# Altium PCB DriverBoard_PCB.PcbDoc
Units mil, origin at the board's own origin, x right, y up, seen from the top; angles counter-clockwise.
Board outline 2560 x 1120 mil, 4 copper layers (Top Layer, GND, PWR, Bottom Layer), stack 62.449 mil thick; 35 components, 27 nets, 120 pads, 83 vias.
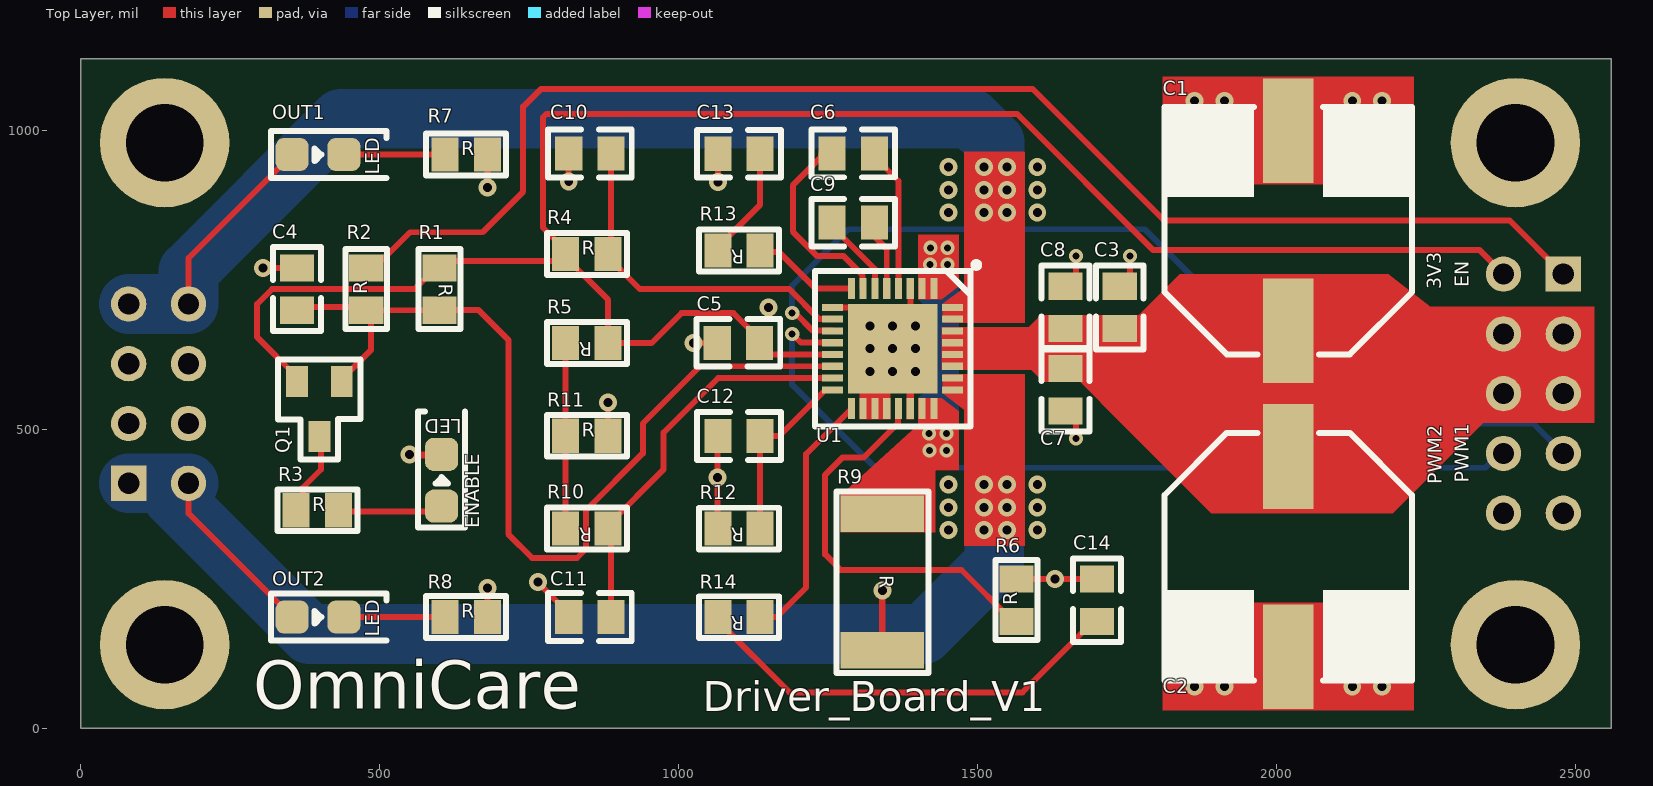
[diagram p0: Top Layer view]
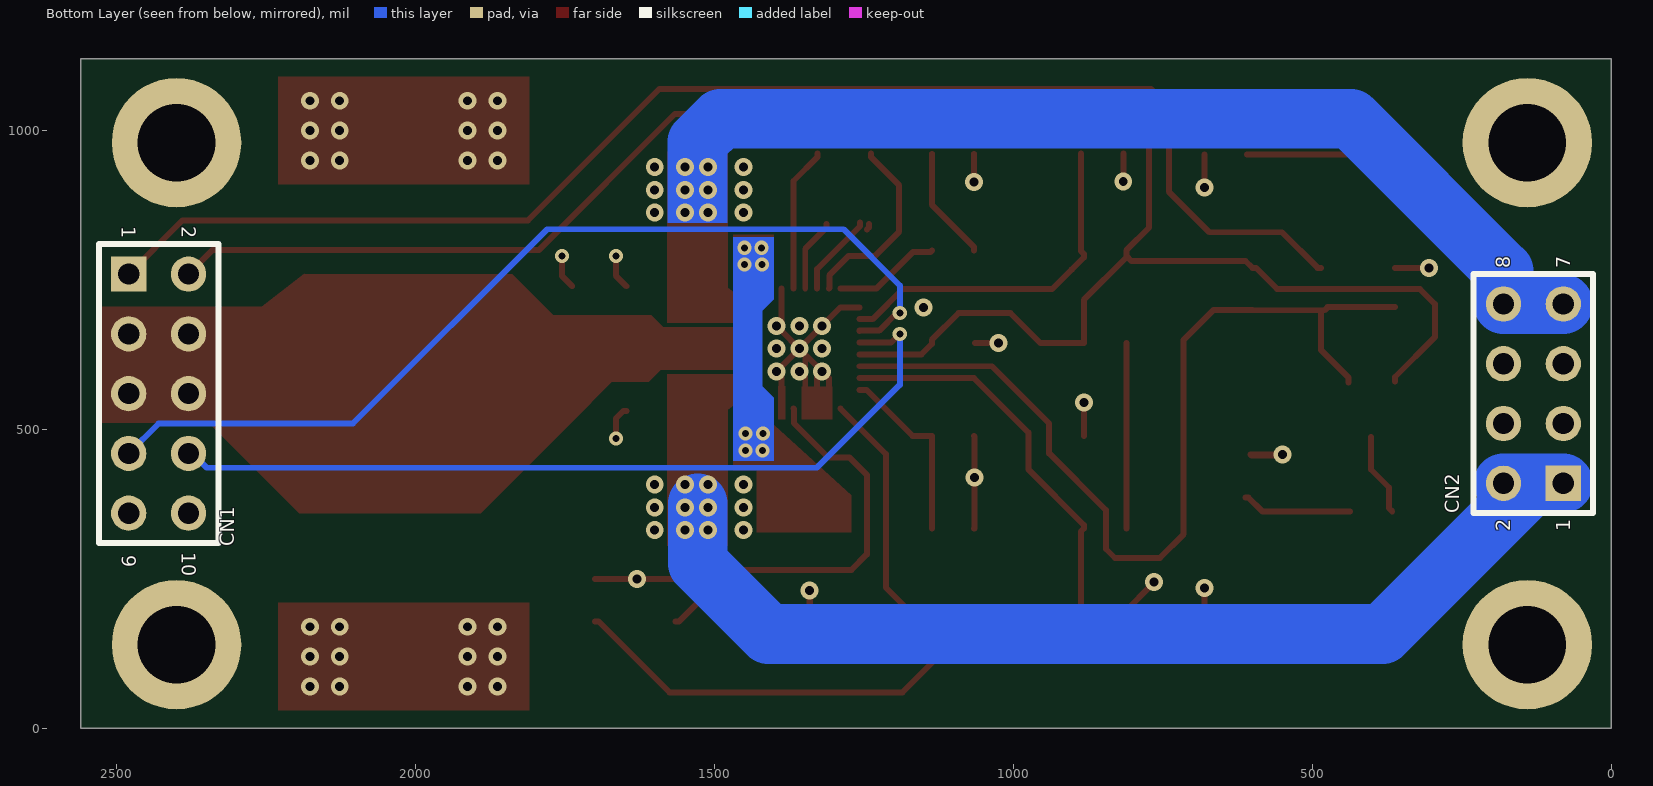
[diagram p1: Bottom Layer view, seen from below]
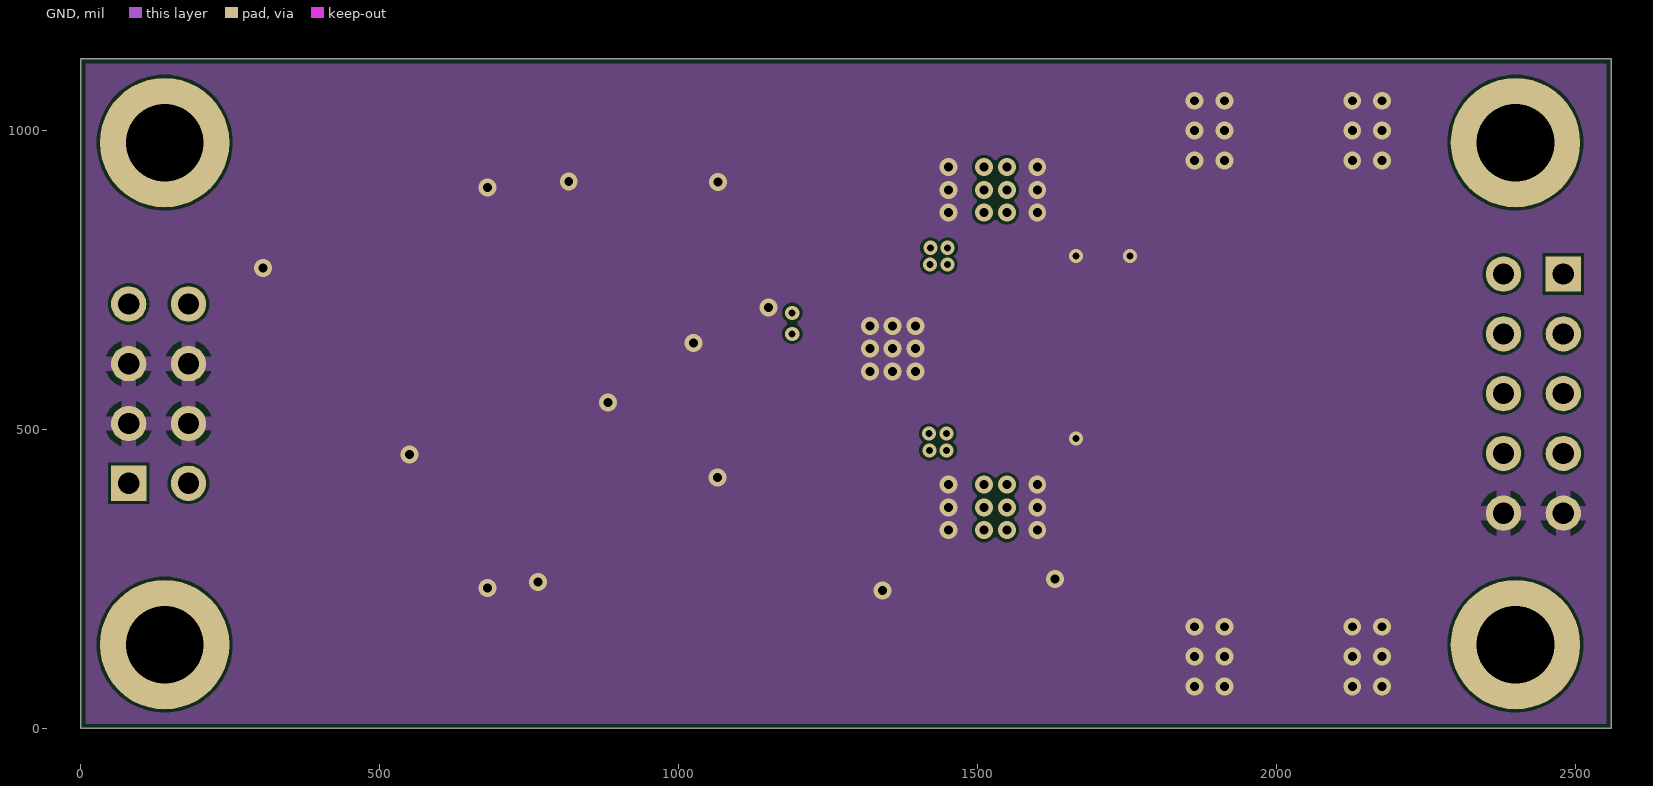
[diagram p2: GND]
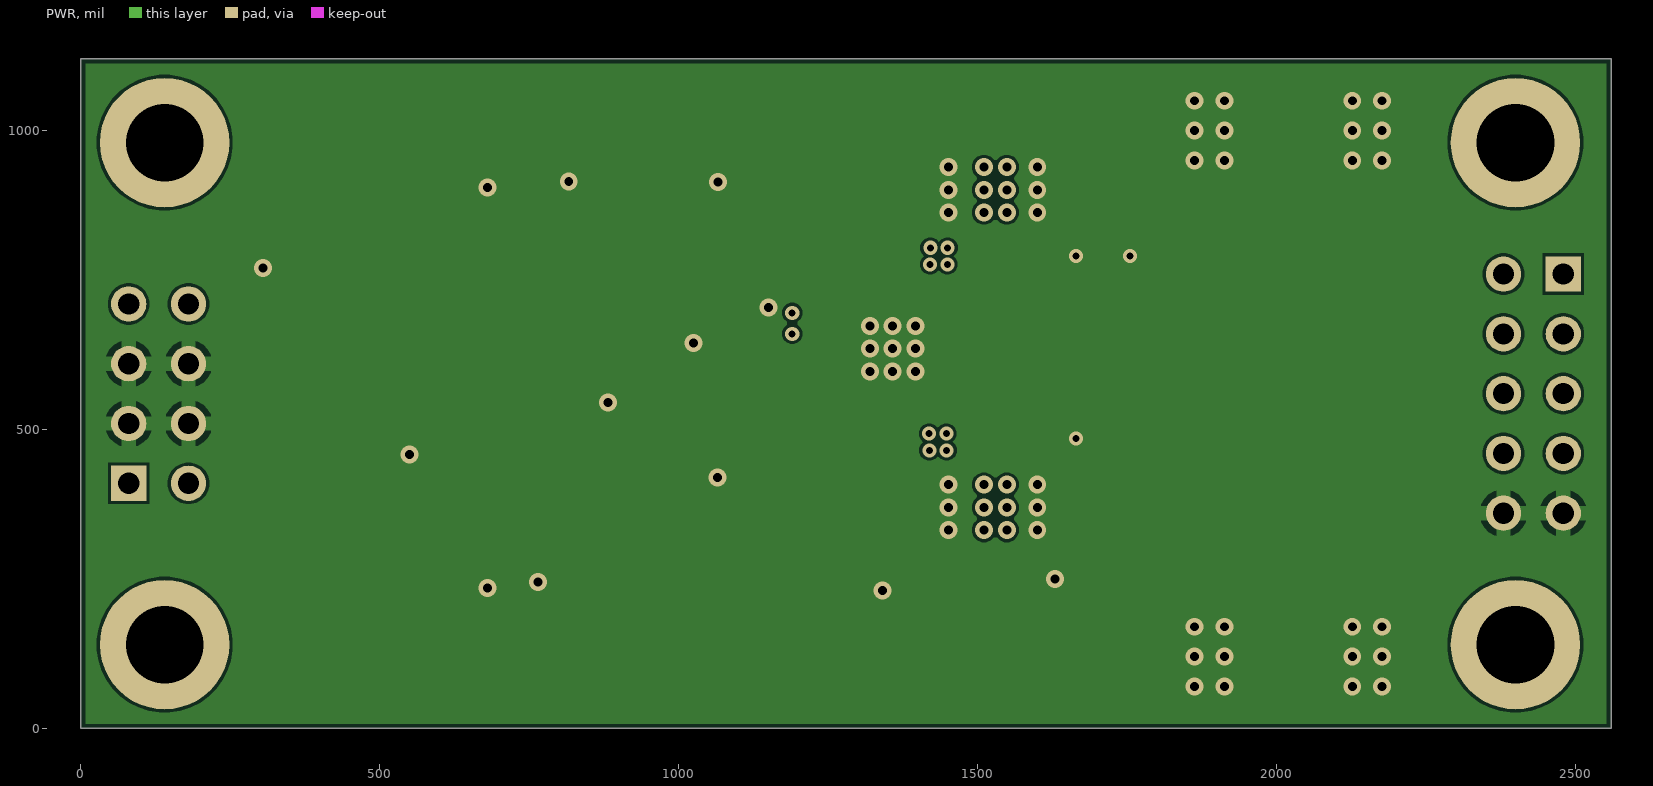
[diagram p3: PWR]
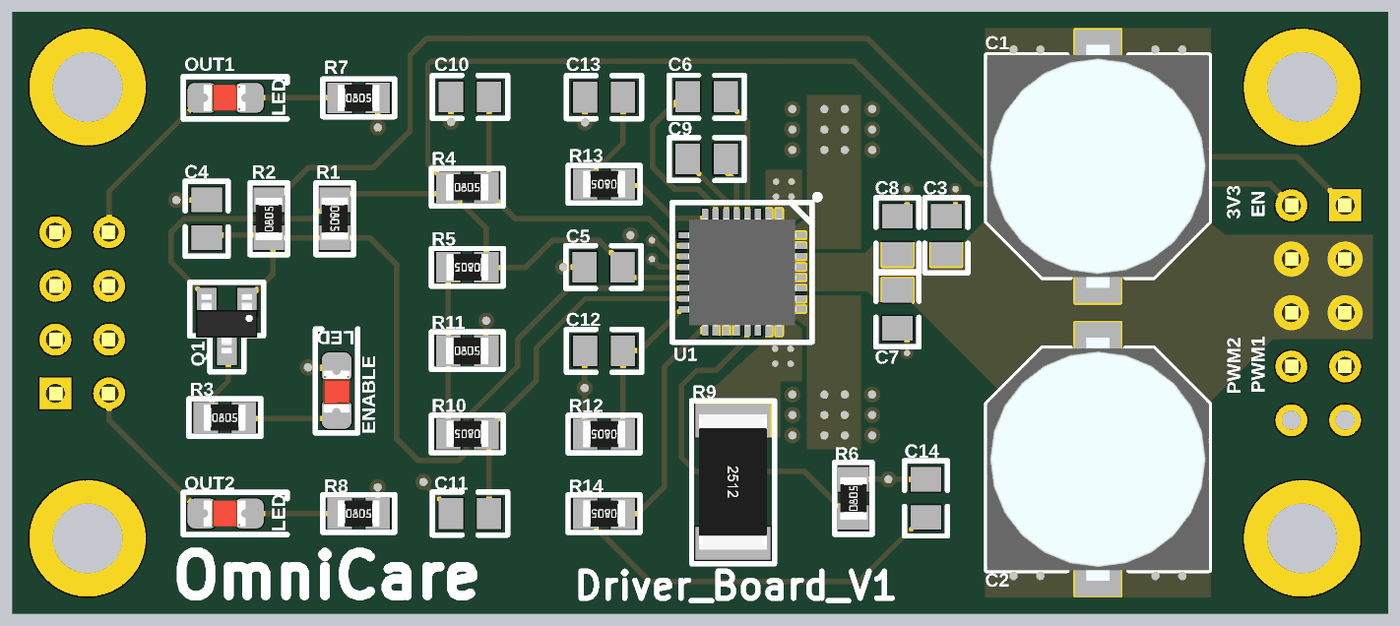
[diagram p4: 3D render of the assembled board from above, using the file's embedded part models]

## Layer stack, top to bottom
Top Solder: solder mask 0.5, Solder Resist, Dk 3.8
Top Layer: signal copper 1.378
Dielectric 1: prepreg 8.2835, 7628, Dk 4.6
GND: signal copper 0.5984
Core: core 41.9291, FR-4, Dk 4.5
PWR: signal copper 0.5984
Dielectric 2: prepreg 8.2835, 7628, Dk 4.6
Bottom Layer: signal copper 1.378
Bottom Solder: solder mask 0.5, Solder Resist, Dk 3.8

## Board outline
0,0 0,1120 2560,1120 2560,0

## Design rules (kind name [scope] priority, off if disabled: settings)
BoardOutlineClearance [All] p1: gap=7.87 ignorepadtopadclearanceinfootprint=FALSE
Clearance [All] p1: gap=5 ignorepadtopadclearanceinfootprint=FALSE except(9.84: Arc-Hole Track-Hole SMDPad-Hole THPad-Hole Via-Hole Fill-Hole Poly-Hole Region-Hole Text-Hole)
ComponentClearance [All] p1: gap=5 collisioncheckmode=3 verticalgap=5 showdistances=TRUE
DiffPairsRouting [All] p1: maxlimit=10 minlimit=5 mostfreqgap=10 toplayer_prefgap=5 toplayer_minwidth=5 toplayer_maxwidth=1000 toplayer_prefwidth=5 midlayer1_mingap=10 midlayer1_minwidth=15 midlayer1_maxwidth=15 midlayer1_prefwidth=15 midlayer2_mingap=10 midlayer2_minwidth=15 midlayer2_maxwidth=15 midlayer2_prefwidth=15 bottomlayer_prefgap=5 bottomlayer_minwidth=5 bottomlayer_maxwidth=1000 bottomlayer_prefwidth=5 maxuncoupledlength=500
Height [All] p1: minheight=0 maxheight=71497.94 prefheight=500
HoleSize [All] p1: absolutevalues=TRUE maxlimit=248.03 minlimit=11.81 maxpercent=80.000 minpercent=20.000
HoleToHoleClearance [All] p1: gap=9.84 allowstackedmicrovias=FALSE
MinimumAnnularRing [All] p1: minimumring=3
MinimumSolderMaskSliver [All] p1: minsoldermaskwidth=0
PlaneClearance [All] p1: clearance=5
PlaneConnect PlaneConnectPowerPads [InPadClass('PowerPads')] p1: planeconnectstyle=Direct reliefexpansion=20 reliefentries=4 reliefconductorwidth=10 reliefairgap=10
PlaneConnect [All] p2: planeconnectstyle=Relief reliefexpansion=11.81 reliefentries=4 reliefconductorwidth=25 reliefairgap=5
PolygonConnect PolygonConnectPowerPads [All vs (InPadClass('PowerPads'))] p1: connectstyle=Direct reliefconductorwidth=10 reliefentries=4 polygonreliefangle="90 Angle" airgapwidth=10
PolygonConnect [All] p2: thpad.connectstyle=Relief thpad.reliefconductorwidth=25 thpad.reliefentries=4 thpad.polygonreliefangle="90 Angle" thpad.airgapwidth=10 smdpad.connectstyle=Relief smdpad.reliefconductorwidth=5 smdpad.reliefentries=4 smdpad.polygonreliefangle="90 Angle" smdpad.airgapwidth=5 via.connectstyle=Direct via.reliefconductorwidth=5 via.reliefentries=4 via.polygonreliefangle="90 Angle" via.airgapwidth=5
RoutingVias [All] p1: holewidth=11.81 width=23.62 viastyle="Through Hole" minholewidth=11.81 minwidth=23.62 maxholewidth=23.62 maxwidth=259.84
SilkToSilkClearance [All] p1: silktosilkclearance=0
SilkToSolderMaskClearance [IsPad] p1: minsilkscreentomaskgap=5 clearancetoexposedcopper=TRUE
SolderMaskExpansion [All] p1: expansion=2.95 istentingtop=FALSE
SupplyNets "Schematic Supply Nets_3" [InNet('GND')] p1: voltage=0.000
SupplyNets "Schematic Supply Nets_2" [InNet('VIN_MOTORS')] p2: voltage=0.000
SupplyNets "Schematic Supply Nets_1" [InNet('+3V3_MCU')] p3: voltage=0.000
Width [All] p1: maxlimit=1000 minlimit=5 preferedwidth=5 midlayer1_maxwidth=10 midlayer2_maxwidth=10 minimp=50.000000 maximp=50.000000 favimp=50.000000
20 further rules are at their usual default settings.

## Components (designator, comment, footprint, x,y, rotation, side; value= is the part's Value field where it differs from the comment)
C1 "220u" "CAP SMD ELE 10x10.2mm" 2018,832.68 r270 top
C2 "220u" "CAP SMD ELE 10x10.2mm" 2022,287.32 r90 top
C3 "100n" "CAP SMD CER 0805" 1738,704.24 r90 top
C4 "10n" "CAP SMD CER 0805" 361.57,734.94 r90 top
C5 "220n" "CAP SMD CER 0805" 1100,645 r180 top
C6 "1u" "CAP SMD CER 0805" 1292,962 r180 top
C7 "470n" "CAP SMD CER 0805" 1647,566.44 r270 top
C8 "470n" "CAP SMD CER 0805" 1647,704.24 r90 top
C9 "100n" "CAP SMD CER 0805" 1292,846 r180 top
C10 "1n" "CAP SMD CER 0805" 851.57,961.65 r180 top
C11 "100n" "CAP SMD CER 0805" 851.57,186.34 r180 top
C12 "1n" "CAP SMD CER 0805" 1101,489.16 r180 top
C13 "100p" "CAP SMD CER 0805" 1101,961.34 r180 top
C14 "100p" "CAP SMD CER 0805" 1700,214.57 r90 top
CN1 "CON HEADER 2.54mm 2x5" "CON HEADER 2.54mm 2x5" 2480,760 r270 bottom
CN2 "Header 2x4 Male" "Header 2x4 Male-Footprint-1" 80,410 r90 bottom
ENABLE "RED" "LED SMD 0805" 603.39,413.39 r90 top
OUT1 "RED" "LED SMD 0805" 395,960 r0 top
OUT2 "RED" "LED SMD 0805" 395,186.34 r0 top
Q1 "BSS84" SOT23 398.97,534.1 r0 top
R1 "39K" "RES SMD 0805" 600,734.94 r270 top
R2 "1K" "RES SMD 0805" 477.29,734.94 r90 top
R3 "330R" "RES SMD 0805" 395.43,365 r0 top
R4 "22K" "RES SMD 0805" 846.5,793.69 r0 top
R5 "330R" "RES SMD 0805" 846.5,644.53 r180 top
R6 "5K" "RES SMD 0805" 1565,214.57 r90 top
R7 "10K" "RES SMD 0805" 644.57,960 r0 top
R8 "10K" "RES SMD 0805" 644.57,186.34 r0 top
R9 "0R05" "RES SMD 2512" 1341,245 r270 top
R10 "13K" "RES SMD 0805" 846.5,334.41 r180 top
R11 "220R" "RES SMD 0805" 846.5,489.47 r0 top
R12 "22K" "RES SMD 0805" 1101,334.09 r180 top
R13 "4K7" "RES SMD 0805" 1101,799.28 r180 top
R14 "4K7" "RES SMD 0805" 1101,186.02 r180 top
U1 "STSPIN958" "NBG32 (VFQFPN 32)" 1358,635.34 r270 top

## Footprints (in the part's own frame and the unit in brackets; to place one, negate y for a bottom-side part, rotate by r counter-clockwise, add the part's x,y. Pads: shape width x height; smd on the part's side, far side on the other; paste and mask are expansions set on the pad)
"CAP SMD CER 0805" [mm] "Ceramicic SMD Capacitor"
  rect 1.15x1.45 smd: 1(-0.9,0) 2(0.9,0)
  silkscreen extent -1.78,-1.02 1.78,1.02, body extent -1,-0.63 1,0.63
"CAP SMD ELE 10x10.2mm" [mm]
  rect 4.45x2.15 smd: 1(4.25,0.051) 2(-4.25,0.051)
  silkscreen extent -5.26,-5.21 5.26,5.31, body extent -5.75,-5.2 5.75,5.3, height 11
"CON HEADER 2.54mm 2x5" [mm]
  rect 1.5x1.5 hole 0.9: 1(0,0)
  round 1.5 hole 0.9: 2(0,2.54) 3(2.54,0) 4(2.54,2.54) 5(5.08,0) 6(5.08,2.54) 7(7.62,0) 8(7.62,2.54) 9(10.16,0) 10(10.16,2.54)
  silkscreen extent -1.27,-1.27 11.43,3.81, body extent -1.27,-1.22 8.89,3.76, height 8.6
"Header 2x4 Male-Footprint-1" [mm]
  rect 1.5x1.5 hole 0.9: 1(0,0)
  round 1.5 hole 0.9: 2(0,2.54) 3(2.54,0) 4(2.54,2.54) 5(5.08,0) 6(5.08,2.54) 7(7.62,0) 8(7.62,2.54)
  silkscreen extent -1.27,-1.27 8.89,3.81, body extent -1.27,-1.22 8.89,3.76, height 8.6
"LED SMD 0805" [mm]
  rrect50% 1.4x1.4 smd: 1(-1.057,0) 2(1.143,0)
  silkscreen extent -1.96,-1 2.96,1, body extent -1,-0.63 1,0.63, height 0.8
"NBG32 (VFQFPN 32)" [mm]
  rect 0.9x0.3 smd: 1(-2.55,1.75) 2(-2.55,1.25) 3(-2.55,0.75) 4(-2.55,0.25) 5(-2.55,-0.25) 6(-2.55,-0.75) 7(-2.55,-1.25) 8(-2.55,-1.75) 17(2.55,-1.75) 18(2.55,-1.25) 19(2.55,-0.75) 20(2.55,-0.25) 21(2.55,0.25) 22(2.55,0.75) 23(2.55,1.25) 24(2.55,1.75)
  rect 0.3x0.9 smd: 9(-1.75,-2.55) 10(-1.25,-2.55) 11(-0.75,-2.55) 12(-0.25,-2.55) 13(0.25,-2.55) 14(0.75,-2.55) 15(1.25,-2.55) 16(1.75,-2.55) 25(1.75,2.55) 26(1.25,2.55) 27(0.75,2.55) 28(0.25,2.55) 29(-0.25,2.55) 30(-0.75,2.55) 31(-1.25,2.55) 32(-1.75,2.55)
  rect 3.8x3.8 smd: 33(0,0)
  silkscreen extent -3.68,-3.3 3.3,3.68, body extent -2.55,-2.55 2.55,2.55, height 1
"RES SMD 0805" [mm]
  rect 1.15x1.45 smd: 1(-0.9,0) 2(0.9,0)
  silkscreen extent -1.7,-0.89 1.7,0.89, body extent -1.01,-0.63 0.99,0.62, height 0.52
"RES SMD 2512" [mm]
  rect 1.55x3.55 smd: 1(-2.9,0) 2(2.9,0)
  silkscreen extent -3.84,-1.96 3.86,1.96, body extent -3.2,-1.6 3.2,1.6, height 0.3
SOT23 [mm]
  rect 0.92x1.32 smd: 1(0.95,1.166) 2(-0.95,1.166) 3(0.003,-1.166)
  silkscreen extent -1.75,-2.13 1.74,2.1, body extent -1.45,-1.27 1.45,1.53, height 1.3

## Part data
C1 C2: library part "CAP SMD - Gen. Electrolytic", "Generic electrolytic capacitors for general purpose."
C3 C4 C5 C6 C7 C8 C9 C10 C11 C12 C13 C14: library part "CAP SMD - Gen. Ceramic 0805", "Generic ceramic capacitor with package 0805 for general purpose."
CN2: library part CMP-00003-1, "Pin Header  2x4 Male 2.54mm"
ENABLE OUT1 OUT2: library part "LED SMD - Gen. 0805", "LED - SMD - 0805", Supplier Part Number 1=C84256
Q1: "TRANSISTOR - Mosfet  P Channel - 130 mA - 50VDS - 20VGS - SOT23"
R1 R2 R3 R4 R5 R6 R7 R8 R10 R11 R12 R13 R14: library part "RES SMD - Gen. 0805", "Generic resistor with package 0805 for general purpose"
R9: library part "RES SMD - Gen. 2512", "Generic resistor with package 2512 for general purpose"
U1: "ST Motor driver up to 58V"

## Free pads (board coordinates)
  round 216.53 hole 129.92: MECH(140,140) MECH(140,980) MECH(2400,140) MECH(2400,980)

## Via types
v1: diameter 30, hole 15, Top Layer to Bottom Layer, tented both sides, 70 vias
v2: diameter 23.62, hole 11.81, Top Layer to Bottom Layer, tented both sides, 13 vias

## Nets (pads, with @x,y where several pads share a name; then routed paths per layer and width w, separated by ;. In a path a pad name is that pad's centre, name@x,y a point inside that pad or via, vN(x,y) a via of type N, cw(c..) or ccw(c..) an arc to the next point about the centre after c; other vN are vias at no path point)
+3V3_MCU: C5.1 CN1.2 Q1.2 R1.1 R4.1 R5.1 U1.13 | length 3276.4
  Top Layer w10: Q1.2 361.57,587.87 295,654.44 295,710 320,735 558.72,735 594.09,770.37 R1.1 611.63,782 802.56,782 811.07,790.51 811.07,787.79 881.94,716.92 R5.1 954.53,644.53 1005,695 1091.56,695 1136.43,650.13 1136.43,643.13 1154.07,625.5 U1.13 ; R4.1 811.07,799.6 773,837.67 773,1022.14 778.86,1028 1566,1028 1794,800 2340,800 CN1.2
EN_MCU: CN1.1 R2.2 | length 2330.7
  Top Layer w10: R2.2@485,770.43 490.91,770.43 550.47,830 672,830 740,898 740,1040 770,1070 1592,1070 1812,850 2390,850 CN1.1
EN_nFAULT: C4.1 Q1.1 R1.2 R2.1 U1.14 | length 1600.2
  Top Layer w10: C4.1@361.57,704.57 474.09,704.57 479.16,699.5 R2.1@485,699.5 ; Q1.1@438.97,578.85 438.97,586.72 485,632.76 R2.1@485,699.5 ; U1.14 1035.81,605.81 940,510 940,460 845,365 845,300 830,285 755,285 715,325 715,650 665.43,699.57 600.06,699.57 R1.2 R2.1@485,699.5
GND: C1.2 C2.2 C3.2 C4.2 C5.2 C7.2 C8.2 C10.2 C11.2 C12.2 C13.2 C14.2 CN1.9 CN1.10 CN2.3 CN2.4 CN2.5 CN2.6 ENABLE.2 R6.2 R7.2 R8.2 R9.2 R11.2 R12.2 U1.3 U1.9 U1.18 U1.19 U1.20 U1.22 U1.33 | length 1817.1
  Top Layer w10: v1(305,770) 361.2,770 C4.2 ; v1(550,458.39) ENABLE.2 601.77,456.77 v1@559.25,456.77 ; R8.2 v1(680,235) ; v1@680,910 R7.2 ; v1(765,245) 765,243.38 816.13,192.24 C11.2 ; v1(816.13,915) C10.2 ; R11.2 v1@881.94,540 ; v1(1025,645) C5.2 ; R12.2 1065,334.66 1065,488.59 C12.2 ; v1(1065.57,914) C13.2 ; U1.9 1289.1,704.24 v1(1358,635.34) ; U1.18 1308.79,586.13 U1.33@1328.47,605.81 ; U1.19 U1.33@1328.47,605.81 ; v1@1340,223 1340,131.83 R9.2 v1(1341,231) v1@1341,223 ; U1.20 U1.33@1348.16,625.5 ; U1.22 1387.53,605.81 v1(1358,635.34) ; U1.3 1387.53,664.87 v1(1358,635.34) ; R6.2 C14.2 ; C7.2 1652.36,531.01 1665,518.37 v2(1665,485) ; C8.2 1647.36,739.67 1665,757.31 v2(1665,790) ; C3.2 1755,756.67 v2(1755,790) ; U1.33@1328.47,605.81 U1.33@1348.16,625.5 ; U1.33@1348.16,625.5 v1(1358,635.34)
  other v1: 1863,70 1913,70 2127,70 2177,70 1863,120 1913,120 2127,120 2177,120 1863,170 1913,170 2127,170 2177,170 1630,250 1451.5,331.68 1600,331.68 1451.5,369.68 1600,369.68 1451.5,407.68 1600,407.68 1065,420 881.94,545 1320,597.34 1358,597.34 1396,597.34 1320,635.34 1396,635.34 1320,673.34 1358,673.34 1396,673.34 1150,704.24 1451.5,863 1600,863 1451.5,901 1600,901 680,905 1451.5,939 1600,939 1863,950 1913,950 2127,950 2177,950 1863,1000 1913,1000 2127,1000 2177,1000 1863,1050 1913,1050 2127,1050 2177,1050
NetC6_1: C6.1 U1.4 | length 243
  Top Layer w10: C6.1 1327.43,956.09 1367.84,915.69 U1.4
NetC6_2: C6.2 U1.7 | length 320.5
  Top Layer w10: C6.2@1238.57,962 1238.57,956.09 1191,908.53 1191,831 1232,790 1276,790 1307.98,758.02 1307.98,736.54 U1.7
NetC9_1: C9.1 U1.5 | length 123.1
  Top Layer w10: C9.1@1312.43,844 1312.43,838.09 1348.16,802.37 U1.5
NetC9_2: C9.2 U1.6 | length 151.2
  Top Layer w10: C9.2@1241.57,844 1241.57,838.09 C9.2@1245.11,834.55 ; C9.2 1256.57,840.09 1328.13,768.53 1328.47,768.53 U1.6
NetC10_1: C10.1 R4.2 U1.10 | length 594.4
  Top Layer w10: C10.1 887,798.76 R4.2 881.94,787.79 902.07,767.65 902.35,767.65 935,735 1185,735 1235.32,684.68 1257.48,684.68 U1.10
NetC11_1: C11.1 R10.1 U1.15 | length 676.7
  Top Layer w10: C11.1@892,191.34 C11.1 887,329.35 R10.1 881.94,340.31 975,433.38 975,495 1066.13,586.13 U1.15
NetC13_1: C13.1 R13.2 | length 191.4
  Top Layer w10: R13.2 1065.57,805.19 1136.43,876.05 C13.1
NetC14_1: C14.1 R14.2 | length 739.4
  Top Layer w10: R14.2 1065.57,180.12 1185.68,60 1574.96,60 1694.09,179.13 C14.1
NetENABLE_1: ENABLE.1 R3.2 | length 184.3
  Top Layer w10: R3.2@437,362.95 583.43,362.95 606.82,386.34 ENABLE.1@611.57,386.34
NetOUT1_2: OUT1.2 R7.1 | length 169.1
  Top Layer w10: OUT1.2 R7.1
NetOUT2_2: OUT2.2 R8.1 | length 169.1
  Top Layer w10: OUT2.2 R8.1
NetQ1_3: Q1.3 R3.1 | length 138.8
  Top Layer w10: R3.1@366.13,362.95 371.57,368.39 371.57,402.95 401.7,433.09 Q1.3@401.7,487.05
NetR5_2: R5.2 R10.2 R11.1 | length 310.1
  Top Layer w10: R10.2 R11.1 R5.2
NetR6_1: R6.1 U1.21 | length 681.8
  Top Layer w10: U1.21 1367.12,534.23 1367.12,510.83 1309.3,453 1274,453 1245,424 1245,291 1271,265 1473.23,265 1559.09,179.13 R6.1
NetR9_1: R9.1 U1.1 U1.2 U1.23 U1.24 | length 284.9
  Top Layer w5: v2(1448,493) v2(1419.14,493) 1419.3,492.84 1419.3,465.3 v2(1419.46,465.14) v2(1448.33,465.14)
  Top Layer w10: R9.1@1407,367.51 1407,503.24 ; 1407.21,503.45 1407.21,515.26 ; U1.23 1407.21,515.26 ; U1.24 1426.9,527.87 1423.49,524.47 1416.42,524.47 1407.21,515.26
  other v2: 1420.81,776.14 1449.67,776.14 1421.14,804 1450,804
NetR13_1: R13.1 U1.8 | length 179
  Top Layer w10: R13.1 1138.93,796.79 1168.21,796.79 1229.27,735.73 U1.8
NetR14_1: R14.1 U1.17 | length 428.1
  Top Layer w10: R14.1 1163.69,186.02 1213,235.34 1213,458.84 U1.17
OUT1: CN2.7 CN2.8 OUT1.1 U1.31 U1.32 | length 2166.9
  Top Layer w10: CN2.8 180,786.61 OUT1.1
  Bottom Layer w10: 1494.45,955.55 v1(1511,939) 1528.5,921.5 ; v1(1511,901) 1528.5,901 v1(1549,901) v1@1538.75,911.25
  Bottom Layer w30: 1528.5,862 1528.5,901
  Bottom Layer w100: CN2.7 CN2.8 180,765 435,1020 1489.75,1020 1528.5,981.25 1528.5,921.5 1528.5,901
  other v1: 1511,863 1549,863 1549,939
OUT2: CN2.1 CN2.2 OUT2.1 U1.25 U1.26 | length 2011.4
  Top Layer w10: CN2.2 180,359.72 OUT2.1
  Bottom Layer w100: CN2.1 CN2.2 ; 155,385 382,158 1410,158 1528,276 1528,376
  other v1: 1511,331.68 1549,331.68 1511,369.68 1549,369.68 1511,407.68 1549,407.68
PWM1: CN1.7 U1.11 | length 1610.4
  Top Layer w10: v2(1190,695) 1194.87,695 1224.43,665.44 1257.03,665.44 U1.11
  Bottom Layer w10: v2(1190,695) 1190,741 1284,835 1780,835 2105,510 2430,510 CN1.7
PWM2: CN1.8 U1.12 | length 1427.7
  Top Layer w10: v2(1190,660) 1204.82,645.18 U1.12
  Bottom Layer w5: CN1.8@2368.73,460 CN1.8
  Bottom Layer w10: v2(1190,660) 1190,574.79 1328.79,436 2349.61,436 2373.61,460 CN1.8
TOFF: C12.1 R12.1 U1.16 | length 308.2
  Top Layer w10: R12.1 C12.1 1168.51,489.16 1245.8,566.44 U1.16
VIN_MOTORS: C1.1 C2.1 C3.1 C7.1 C8.1 CN1.3 CN1.4 CN1.5 CN1.6 U1.27 U1.28 U1.29 U1.30

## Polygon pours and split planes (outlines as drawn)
GND on GND "GND_L02_P003" (solid, pour order 3): 0,0 2560,0 2560,1120 0,1120
GND on PWR "GND_L03_P007" (solid, pour order 7): 1,-3 4,0 2560,0 2560,1120 0,1120

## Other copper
Top Layer:
  region net NetR9_1: 1401.01,507.99 1390,498 1271,389.97 1271,328 1429,328 1429,445
  region net NetR9_1: 1434,552.68 1440,552.68 1469,530.68 1469,462.68 1434,462.68
  region net NetR9_1: 1434,552.68 1401,552.68 1401,495.68 1424.5,472.18 1434,462.68
  region net NetR9_1: 1401,495.68 1401,432 1469,432 1469,464.68
  region net OUT2: 1441.5,560.34 1441.5,592.34 1579,592.34 1579,305.68 1478,305.68 1478,533.22
  region net VIN_MOTORS: 2532,511 2346,511 2195,360 1891,360 1740,511 1672,580 1610,580 1590,600 1440,600 1440,671 1586,671 1606,691 1771,691 1771,692 1838.36,759.36 2186.17,760.59 2257.3,705 2532,705
  region net NetR9_1: 1401,775 1401,826 1469,826 1469,806
  region net NetR9_1: 1434,718 1401,718 1401,775 1424.5,798.5 1434,808
  region net NetR9_1: 1434,718 1440,718 1469,740 1469,808 1434,808
  region net GND: 1810,210 2230,210 2230,30 1810,30
  region net OUT1: 1441.5,710.34 1441.5,678.34 1579,678.34 1579,965 1478,965 1478,737.45
  region net GND: 1810,1090 2230,1090 2230,910 1810,910
  region net GND: 1382,517.34 1393,517.34 1393,572.34 1382,572.34
  region net GND: 1354,517.34 1303,517.34 1303,571.34 1354,571.34
Bottom Layer:
  region net OUT1: 1479,915 1479,846 1578,846 1578,915
  region net NetR9_1: 1401,761 1401,718 1420,699 1420,572 1401,553 1401,448 1469,448 1469,761
  region net NetR9_1: 1469,822 1401,822 1401,761 1402,761 1469,761

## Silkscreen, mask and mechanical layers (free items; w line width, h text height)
Top Overlay:
  text "EN" at 2330,737.92 h40 r90
  text "3V3" at 2284.53,734.65 h40 r90
  text "PWM1" at 2330,410.64 h40 r90
  text "PWM2" at 2285,408.63 h40 r90
  text "OmniCare" at 288,33 h80
  text "Driver_Board_V1" at 1040,28.33 h50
